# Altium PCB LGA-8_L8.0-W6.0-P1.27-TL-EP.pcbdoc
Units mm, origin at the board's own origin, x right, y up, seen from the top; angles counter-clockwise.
Board outline 22.11 x 18.76 mm, 2 copper layers (Top Layer, Bottom Layer), stack 0 mm thick; 1 components, 0 nets, 9 pads, 0 vias.
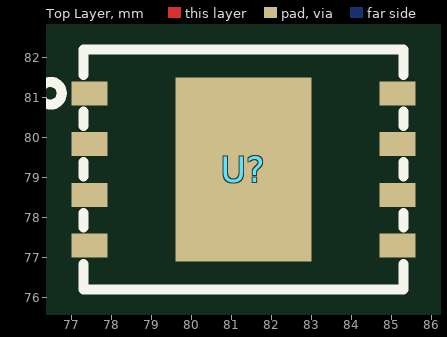
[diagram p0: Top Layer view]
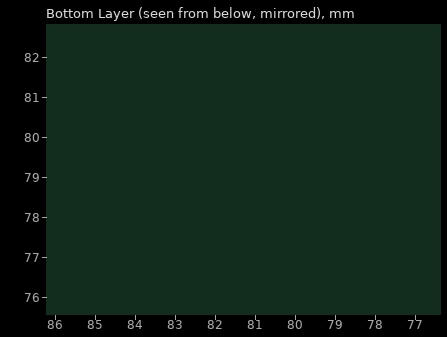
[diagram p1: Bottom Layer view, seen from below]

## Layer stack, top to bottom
Top Layer: signal copper (thickness not stored)
Bottom Layer: signal copper (thickness not stored)

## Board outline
91.96,69.85 69.85,69.85 69.85,88.61 91.96,88.61

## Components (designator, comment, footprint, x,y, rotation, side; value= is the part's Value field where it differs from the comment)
U? "" LGA-8_L8.0-W6.0-P1.27-TL-EP 81.31,79.2 r0 top

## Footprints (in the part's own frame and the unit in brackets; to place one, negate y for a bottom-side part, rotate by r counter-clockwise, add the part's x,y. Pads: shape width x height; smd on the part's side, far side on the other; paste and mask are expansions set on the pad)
LGA-8_L8.0-W6.0-P1.27-TL-EP [mm]
  rect 0.9x0.6 smd paste+0 mask+0.05: 1(-3.85,1.905) 2(-3.85,0.635) 3(-3.85,-0.635) 4(-3.85,-1.905) 5(3.85,-1.905) 6(3.85,-0.635) 7(3.85,0.635) 8(3.85,1.905)
  rect 3.4x4.6 smd paste+0 mask+0.05: 9(0,0)
  silkscreen extent -5.11,-3 4,3

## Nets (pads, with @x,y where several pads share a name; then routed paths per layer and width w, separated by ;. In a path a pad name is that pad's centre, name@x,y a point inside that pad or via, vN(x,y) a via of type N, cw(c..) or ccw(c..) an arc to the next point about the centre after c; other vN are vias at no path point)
pads on no net: U?.1 U?.2 U?.3 U?.4 U?.5 U?.6 U?.7 U?.8 U?.9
